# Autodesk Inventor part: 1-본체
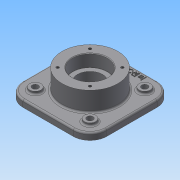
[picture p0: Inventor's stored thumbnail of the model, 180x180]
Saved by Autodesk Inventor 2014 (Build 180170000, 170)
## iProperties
Created: 2015-09
Part Number: 1-본체
Material: Generic
Document SubType Name: Modeling
Designer: study
Density: 1 g/cm^3
Appearance: Default
Author: study
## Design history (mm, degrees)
sketch "스케치1"
  geometry: L1 (-75, 75)-(75, 75); L2 (75, 75)-(75, -75); L3 (75, -75)-(-75, -75); L4 (-75, -75)-(-75, 75); L5 (-75, 75)-(75, -75); L6 (75, 75)-(-75, -75); 1 further point
  constraints: 12 end point, 2 midpoint, 2 parallel, 1 horizontal, 1 perpendicular
  dimensions: "d0" = 150 distance of L1.start L1.end; "d1" = 150 distance of L1.end L2.end
extrude "돌출1" new body sketch "스케치1" distance "d2" = 12; taper "d3" = 0 deg
sketch "스케치2"
  geometry: C1 r 50 at (0, 0); 1 further point
  constraints: 1 centre point, 1 coincident
  dimensions: "d4" = 100 diameter of C1
extrude "돌출2" join sketch "스케치2" distance "d5" = 35; taper "d6" = 0 deg
sketch "스케치3"
  geometry: C1 r 50 at (0, 0); 1 further point
  constraints: 1 centre point, 1 coincident
  dimensions: "d7" = 100 diameter of C1
extrude "돌출3" join sketch "스케치3" distance "d8" = 23; taper "d9" = 0 deg
sketch "스케치4"
  geometry: C1 r 50 at (0, 0) reference; 1 further point
  constraints: 1 coincident
hole "구멍1" sketch "스케치4" at (0, 0) diameter "d10" = 45; stored, may be unused: countersink angle "d14" = 90 deg, drill point angle "d16" = 118 deg; dims "d11" = 6, "d12" = 62, "d13" = 22, "d15" = 8
sketch "스케치5"
  geometry: C1 r 50 at (0, 0) reference; 1 further point
  constraints: 1 coincident
hole "구멍2" sketch "스케치5" at (0, 0) diameter "d17" = 45; stored, may be unused: countersink angle "d21" = 90 deg, drill point angle "d23" = 118 deg; dims "d18" = 6, "d19" = 62, "d20" = 22, "d22" = 8
sketch "스케치6"
  geometry: L1 (-49, 49)-(49, 49); L2 (49, 49)-(49, -49); L3 (49, -49)-(-49, -49); L4 (-49, -49)-(-49, 49); L5 (-49, 49)-(49, -49); L6 (49, 49)-(-49, -49); C1 r 50 at (0, 0) reference; C2 r 10 at (-49, 49); C3 r 10 at (49, 49); C4 r 10 at (49, -49); C5 r 10 at (-49, -49)
  constraints: 12 end point, 4 centre point, 4 coincident, 3 equal radius, 2 midpoint, 2 parallel, 1 horizontal, 1 perpendicular
  dimensions: "d24" = 98 distance of L1.start L1.end; "d25" = 98 distance of L1.end L2.end; "d26" = 20 diameter of C2
extrude "돌출4" join sketch "스케치6" distance "d27" = 5; taper "d28" = 0 deg
sketch "스케치7"
  geometry: C1 r 10 at (0, 0) reference; C2 r 10 at (98, 0) reference; C3 r 10 at (0, -98) reference; C4 r 10 at (98, -98) reference; 5 further points
  constraints: 4 coincident
hole "구멍3" sketch "스케치7" at (0, 0), (0, -98), (98, -98), (98, 0) diameter "d29" = 11; stored, may be unused: countersink angle "d33" = 90 deg, drill point angle "d35" = 118 deg; dims "d30" = 6, "d31" = 62, "d32" = 22, "d34" = 8
sketch "스케치8"
  geometry: L1 (-28.991, 28.991)-(28.991, 28.991); L2 (28.991, 28.991)-(28.991, -28.991); L3 (28.991, -28.991)-(-28.991, -28.991); L4 (-28.991, -28.991)-(-28.991, 28.991); L5 (-28.991, 28.991)-(28.991, -28.991); L6 (28.991, 28.991)-(-28.991, -28.991); C1 r 50 at (0, 0) reference; 4 further points
  constraints: 12 end point, 4 coincident, 2 midpoint, 2 parallel, 2 perpendicular, 1 horizontal
  dimensions: "d36" = 82 distance of L1.end L3.end
hole "구멍4" sketch "스케치8" at (-28.991, 28.991), (-28.991, -28.991), (28.991, -28.991), (28.991, 28.991) diameter "d37" = 4.917; stored, may be unused: countersink angle "d41" = 90 deg, drill point angle "d43" = 118 deg; dims "d38" = 10, "d39" = 62, "d40" = 22, "d42" = 13
sketch "스케치9"
  geometry: L1 (-28.991, 28.991)-(28.991, 28.991); L2 (28.991, 28.991)-(28.991, -28.991); L3 (28.991, -28.991)-(-28.991, -28.991); L4 (-28.991, -28.991)-(-28.991, 28.991); L5 (-28.991, 28.991)-(28.991, -28.991); L6 (28.991, 28.991)-(-28.991, -28.991); C1 r 50 at (0, 0) reference; 4 further points
  constraints: 12 end point, 4 coincident, 2 midpoint, 2 parallel, 2 perpendicular, 1 horizontal
  dimensions: "d44" = 82 distance of L1.end L3.end
hole "구멍5" sketch "스케치9" at (-28.991, 28.991), (-28.991, -28.991), (28.991, -28.991), (28.991, 28.991) diameter "d45" = 4.917; stored, may be unused: countersink angle "d49" = 90 deg, drill point angle "d51" = 118 deg; dims "d46" = 10, "d47" = 62, "d48" = 22, "d50" = 13
fillet "모깎기1" dims "d52" = 30
fillet "모깎기2" dims "d53" = 0.3
chamfer "모따기1" distance "d54" = 1; stored, may be unused: second distance "d55" = 2, angle "d56" = 45 deg
fillet "모깎기3" dims "d57" = 3
fillet "모깎기4" dims "d58" = 3
fillet "모깎기5" dims "d59" = 3
sketch "스케치10"
  geometry: C1 r 53 at (0, 0) reference; 1 further point
  constraints: 1 vertical alignment, 1 other
  dimensions: "d60" = 65 distance of C1.centre point (0, 65)
feature "엠보싱1" sketch "스케치10" dims "d61" = 1, "d62" = 0
node "솔리드1"
node "투영된 루프1"
node "투영된 루프2"
node "투영된 루프3"
